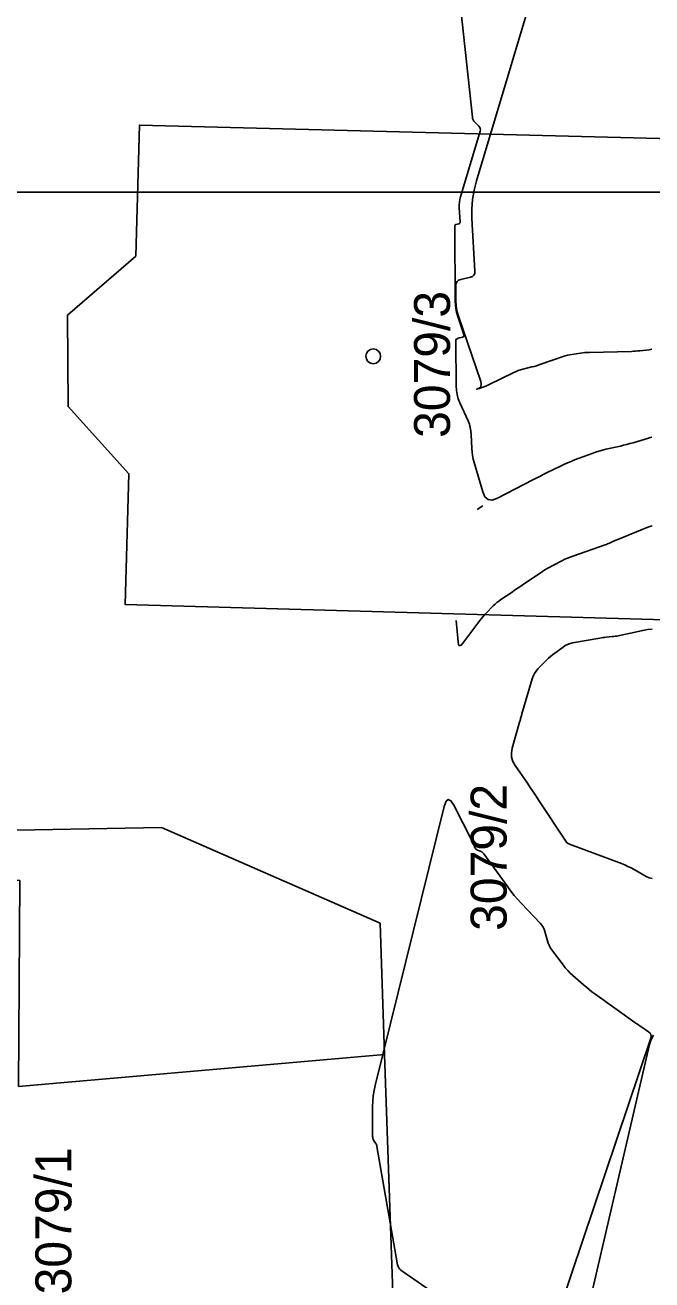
# Model space of a CAD drawing. Extents: x -534410 to -534262, y -1190162 to -1189584.
# Drawn here: x -534360.56 to -534345.75, y -1190135.2 to -1190105.52 of the extents above; entities that cross this region are included whole.
import ezdxf

# ---------------------------------------------------------------- set-up
doc = ezdxf.new("R2010")
doc.units = 0
for name, color, linetype in [('30', 7, 'Continuous'), ('31', 7, 'Continuous'), ('_rámeček', 7, 'Continuous'), ('Hranice parcel', 7, 'Continuous'), ('Parcelní čísla', 7, 'Continuous'), ('Polygon budovy', 7, 'Continuous'), ('Značky budov', 7, 'Continuous')]:
    doc.layers.add(name, color=color, linetype=linetype)

msp = doc.modelspace()

# ---------------------------------------------------------------- linework, layer by layer
at = {"layer": '30'}
for points in [[(-534350.446, -1190103.47), (-534349.99, -1190107.693), (-534349.983, -1190107.727), (-534349.972, -1190107.757), (-534349.955, -1190107.785), (-534349.933, -1190107.811), (-534349.835, -1190107.909), (-534349.815, -1190107.935), (-534349.804, -1190107.962), (-534349.801, -1190107.992), (-534349.806, -1190108.024), (-534350.271, -1190109.58), (-534350.286, -1190109.641), (-534350.296, -1190109.702), (-534350.301, -1190109.765), (-534350.3, -1190109.828), (-534350.28, -1190110.176), (-534350.281, -1190110.19), (-534350.287, -1190110.202), (-534350.296, -1190110.211), (-534350.31, -1190110.216), (-534350.375, -1190110.23), (-534350.389, -1190110.236), (-534350.399, -1190110.244), (-534350.405, -1190110.256), (-534350.406, -1190110.271), (-534350.396, -1190112.051), (-534350.392, -1190112.137), (-534350.381, -1190112.222), (-534350.364, -1190112.306), (-534350.339, -1190112.389), (-534350.189, -1190112.831), (-534350.185, -1190112.855), (-534350.189, -1190112.873), (-534350.203, -1190112.887), (-534350.224, -1190112.897), (-534350.329, -1190112.924), (-534350.352, -1190112.934), (-534350.369, -1190112.948), (-534350.378, -1190112.968), (-534350.381, -1190112.992), (-534350.374, -1190114.052), (-534350.368, -1190114.156), (-534350.351, -1190114.258), (-534350.323, -1190114.358), (-534350.285, -1190114.455), (-534350.092, -1190114.877), (-534350.061, -1190114.955), (-534350.038, -1190115.034), (-534350.023, -1190115.115), (-534350.016, -1190115.198), (-534350.003, -1190115.533), (-534349.998, -1190115.617), (-534349.987, -1190115.699), (-534349.971, -1190115.781), (-534349.95, -1190115.862), (-534349.746, -1190116.559), (-534349.693, -1190116.675), (-534349.617, -1190116.739), (-534349.519, -1190116.75), (-534349.398, -1190116.708), (-534348.559, -1190116.274), (-534348.478, -1190116.232), (-534348.397, -1190116.191), (-534348.316, -1190116.15), (-534348.234, -1190116.11), (-534347.907, -1190115.948), (-534347.824, -1190115.909), (-534347.741, -1190115.872), (-534347.657, -1190115.837), (-534347.572, -1190115.803), (-534347.158, -1190115.648), (-534347.078, -1190115.619), (-534346.998, -1190115.594), (-534346.916, -1190115.571), (-534346.834, -1190115.551), (-534346.49, -1190115.474), (-534346.415, -1190115.456), (-534346.339, -1190115.437), (-534346.264, -1190115.417), (-534346.19, -1190115.395), (-534345.827, -1190115.286), (-534345.785, -1190115.274), (-534345.743, -1190115.262)], [(-534349.743, -1190116.887), (-534349.876, -1190116.977)], [(-534345.74, -1190125.703), (-534345.813, -1190125.688), (-534345.884, -1190125.656), (-534346.167, -1190125.492), (-534346.238, -1190125.452), (-534346.311, -1190125.416), (-534346.385, -1190125.382), (-534346.461, -1190125.352), (-534347.692, -1190124.889), (-534347.703, -1190124.885), (-534347.713, -1190124.88), (-534347.74, -1190124.868), (-534347.743, -1190124.866), (-534347.746, -1190124.864), (-534347.754, -1190124.855), (-534347.763, -1190124.843), (-534347.796, -1190124.794), (-534347.81, -1190124.773), (-534348.415, -1190123.857), (-534348.483, -1190123.755), (-534348.552, -1190123.653), (-534348.621, -1190123.551), (-534348.69, -1190123.45), (-534348.979, -1190123.033), (-534349.032, -1190122.937), (-534349.061, -1190122.836), (-534349.066, -1190122.732), (-534349.047, -1190122.624), (-534348.874, -1190122.009), (-534348.867, -1190121.985), (-534348.861, -1190121.962), (-534348.855, -1190121.939), (-534348.848, -1190121.916), (-534348.824, -1190121.823), (-534348.817, -1190121.8), (-534348.811, -1190121.776), (-534348.804, -1190121.753), (-534348.798, -1190121.73), (-534348.577, -1190120.979), (-534348.554, -1190120.914), (-534348.523, -1190120.853), (-534348.485, -1190120.797), (-534348.439, -1190120.745), (-534348.23, -1190120.532), (-534348.186, -1190120.489), (-534348.14, -1190120.448), (-534348.092, -1190120.409), (-534348.043, -1190120.372), (-534347.843, -1190120.227), (-534347.792, -1190120.194), (-534347.738, -1190120.167), (-534347.681, -1190120.146), (-534347.621, -1190120.132), (-534346.975, -1190120.017), (-534346.939, -1190120.011), (-534346.903, -1190120.006), (-534346.866, -1190120.001), (-534346.83, -1190119.997), (-534346.685, -1190119.982), (-534346.649, -1190119.978), (-534346.613, -1190119.973), (-534346.577, -1190119.967), (-534346.541, -1190119.96), (-534345.96, -1190119.834), (-534345.851, -1190119.815), (-534345.742, -1190119.802)]]:
    msp.add_lwpolyline(points, dxfattribs=at)
at = {"layer": '31'}
for points in [[(-534348.233, -1190103.639), (-534349.895, -1190109.203), (-534349.95, -1190109.422), (-534349.986, -1190109.643), (-534350.002, -1190109.867), (-534349.999, -1190110.092), (-534349.928, -1190111.336), (-534349.932, -1190111.389), (-534349.952, -1190111.431), (-534349.987, -1190111.461), (-534350.036, -1190111.48), (-534350.266, -1190111.533), (-534350.316, -1190111.551), (-534350.352, -1190111.582), (-534350.374, -1190111.623), (-534350.38, -1190111.677), (-534350.378, -1190112.056), (-534350.374, -1190112.138), (-534350.364, -1190112.219), (-534350.347, -1190112.299), (-534350.324, -1190112.378), (-534349.793, -1190113.945), (-534349.78, -1190114.012), (-534349.793, -1190114.065), (-534349.83, -1190114.104), (-534349.892, -1190114.131), (-534349.818, -1190114.109), (-534349.746, -1190114.084), (-534349.675, -1190114.056), (-534349.605, -1190114.023), (-534349.006, -1190113.73), (-534348.956, -1190113.707), (-534348.904, -1190113.687), (-534348.852, -1190113.669), (-534348.798, -1190113.655), (-534348.582, -1190113.602), (-534348.528, -1190113.588), (-534348.475, -1190113.573), (-534348.422, -1190113.556), (-534348.369, -1190113.538), (-534347.842, -1190113.353), (-534347.792, -1190113.337), (-534347.742, -1190113.323), (-534347.691, -1190113.312), (-534347.639, -1190113.304), (-534347.432, -1190113.274), (-534347.38, -1190113.267), (-534347.328, -1190113.262), (-534347.276, -1190113.259), (-534347.224, -1190113.257), (-534346.227, -1190113.233), (-534346.178, -1190113.232), (-534346.13, -1190113.229), (-534346.081, -1190113.225), (-534346.033, -1190113.22), (-534345.811, -1190113.194), (-534345.777, -1190113.189), (-534345.744, -1190113.183)], [(-534350.37, -1190119.598), (-534350.328, -1190120.104), (-534350.316, -1190120.17), (-534350.293, -1190120.197), (-534350.258, -1190120.186), (-534350.213, -1190120.137), (-534349.813, -1190119.601), (-534349.777, -1190119.555), (-534349.74, -1190119.51), (-534349.701, -1190119.466), (-534349.661, -1190119.424), (-534349.496, -1190119.257), (-534349.454, -1190119.216), (-534349.411, -1190119.178), (-534349.365, -1190119.142), (-534349.317, -1190119.107), (-534349.052, -1190118.927), (-534348.991, -1190118.886), (-534348.931, -1190118.845), (-534348.87, -1190118.804), (-534348.81, -1190118.763), (-534348.332, -1190118.442), (-534348.276, -1190118.405), (-534348.219, -1190118.37), (-534348.16, -1190118.337), (-534348.101, -1190118.305), (-534347.862, -1190118.182), (-534347.802, -1190118.152), (-534347.741, -1190118.124), (-534347.679, -1190118.099), (-534347.616, -1190118.076), (-534346.847, -1190117.808), (-534346.822, -1190117.799), (-534346.797, -1190117.79), (-534346.772, -1190117.78), (-534346.748, -1190117.769), (-534346.65, -1190117.725), (-534346.626, -1190117.714), (-534346.601, -1190117.703), (-534346.577, -1190117.693), (-534346.552, -1190117.683), (-534345.84, -1190117.394), (-534345.791, -1190117.376), (-534345.742, -1190117.358)], [(-534350.829, -1190135.561), (-534351.449, -1190135.128), (-534351.547, -1190135.06), (-534351.678, -1190134.969), (-534351.707, -1190134.944), (-534351.73, -1190134.915), (-534351.747, -1190134.882), (-534351.757, -1190134.845), (-534352.247, -1190132.042), (-534352.252, -1190132.021), (-534352.259, -1190132.001), (-534352.268, -1190131.981), (-534352.278, -1190131.962), (-534352.325, -1190131.889), (-534352.335, -1190131.87), (-534352.343, -1190131.85), (-534352.347, -1190131.83), (-534352.348, -1190131.808), (-534352.348, -1190131.094), (-534352.345, -1190130.968), (-534352.333, -1190130.843), (-534352.314, -1190130.719), (-534352.288, -1190130.596), (-534350.656, -1190123.997), (-534350.612, -1190123.876), (-534350.56, -1190123.831), (-534350.498, -1190123.863), (-534350.428, -1190123.97), (-534350.001, -1190124.804), (-534349.99, -1190124.824), (-534349.981, -1190124.845), (-534349.972, -1190124.866), (-534349.963, -1190124.887), (-534349.929, -1190124.971), (-534349.919, -1190124.991), (-534349.906, -1190125.007), (-534349.89, -1190125.021), (-534349.87, -1190125.031), (-534349.785, -1190125.064), (-534349.765, -1190125.074), (-534349.747, -1190125.086), (-534349.731, -1190125.101), (-534349.717, -1190125.118), (-534349.155, -1190125.901), (-534349.079, -1190126.003), (-534349, -1190126.102), (-534348.917, -1190126.199), (-534348.831, -1190126.292), (-534348.384, -1190126.762), (-534348.348, -1190126.805), (-534348.317, -1190126.851), (-534348.293, -1190126.902), (-534348.275, -1190126.955), (-534348.215, -1190127.176), (-534348.198, -1190127.231), (-534348.176, -1190127.282), (-534348.149, -1190127.332), (-534348.117, -1190127.379), (-534347.844, -1190127.748), (-534347.792, -1190127.815), (-534347.736, -1190127.879), (-534347.677, -1190127.939), (-534347.615, -1190127.997), (-534347.359, -1190128.221), (-534347.295, -1190128.276), (-534347.229, -1190128.33), (-534347.162, -1190128.382), (-534347.093, -1190128.432), (-534346.145, -1190129.11), (-534346.105, -1190129.139), (-534346.065, -1190129.167), (-534346.025, -1190129.194), (-534345.985, -1190129.222), (-534345.824, -1190129.332), (-534345.79, -1190129.361), (-534345.771, -1190129.396), (-534345.766, -1190129.435), (-534345.774, -1190129.479), (-534347.917, -1190135.848)], [(-534345.705, -1190129.413), (-534345.762, -1190129.514), (-534345.799, -1190129.628), (-534347.323, -1190136.18)]]:
    msp.add_lwpolyline(points, dxfattribs=at)
at = {"layer": '_rámeček'}
msp.add_lwpolyline([(-534410.126, -1190004.47), (-534261.626, -1190004.47), (-534261.626, -1190109.47), (-534410.126, -1190109.47)], close=True, dxfattribs=at)
at = {"layer": 'Hranice parcel'}
for points in [[(-534343.41, -1190108.25), (-534357.86, -1190107.88), (-534357.95, -1190110.98), (-534359.56, -1190112.38), (-534359.55, -1190114.54), (-534358.11, -1190116.13), (-534358.2, -1190119.22), (-534343.76, -1190119.63)], [(-534351.82, -1190136.86), (-534352.07, -1190129.87), (-534352.17, -1190126.76), (-534357.34, -1190124.5), (-534362.92, -1190124.6), (-534362.95, -1190121.17), (-534367.57, -1190121.12)]]:
    msp.add_lwpolyline(points, dxfattribs=at)
at = {"layer": 'Polygon budovy'}
for points in [[(-534343.7, -1190117.89), (-534343.41, -1190108.25), (-534357.86, -1190107.88), (-534357.95, -1190110.98), (-534359.56, -1190112.38), (-534359.55, -1190114.54), (-534358.11, -1190116.13), (-534358.2, -1190119.22), (-534343.76, -1190119.63)], [(-534351.82, -1190136.86), (-534352.07, -1190129.87), (-534360.72, -1190130.62), (-534360.69, -1190125.75), (-534363.02, -1190125.69), (-534362.92, -1190124.6), (-534362.95, -1190121.17), (-534367.57, -1190121.12), (-534367.61, -1190129.31), (-534367.59, -1190138.36)]]:
    msp.add_lwpolyline(points, close=True, dxfattribs=at)
at = {"layer": 'Značky budov'}
msp.add_circle((-534352.334, -1190113.351), 0.175, dxfattribs=at)

# ---------------------------------------------------------------- texts
at = {"layer": 'Parcelní čísla'}
for s, p in [('3079/3', (-534350.519, -1190115.281)), ('3079/2', (-534349.18, -1190126.942)), ('3079/1', (-534359.471, -1190135.541))]:
    msp.add_text(s, height=0.85, rotation=90, dxfattribs=at).set_placement(p)

doc.saveas('drawing.dxf')
